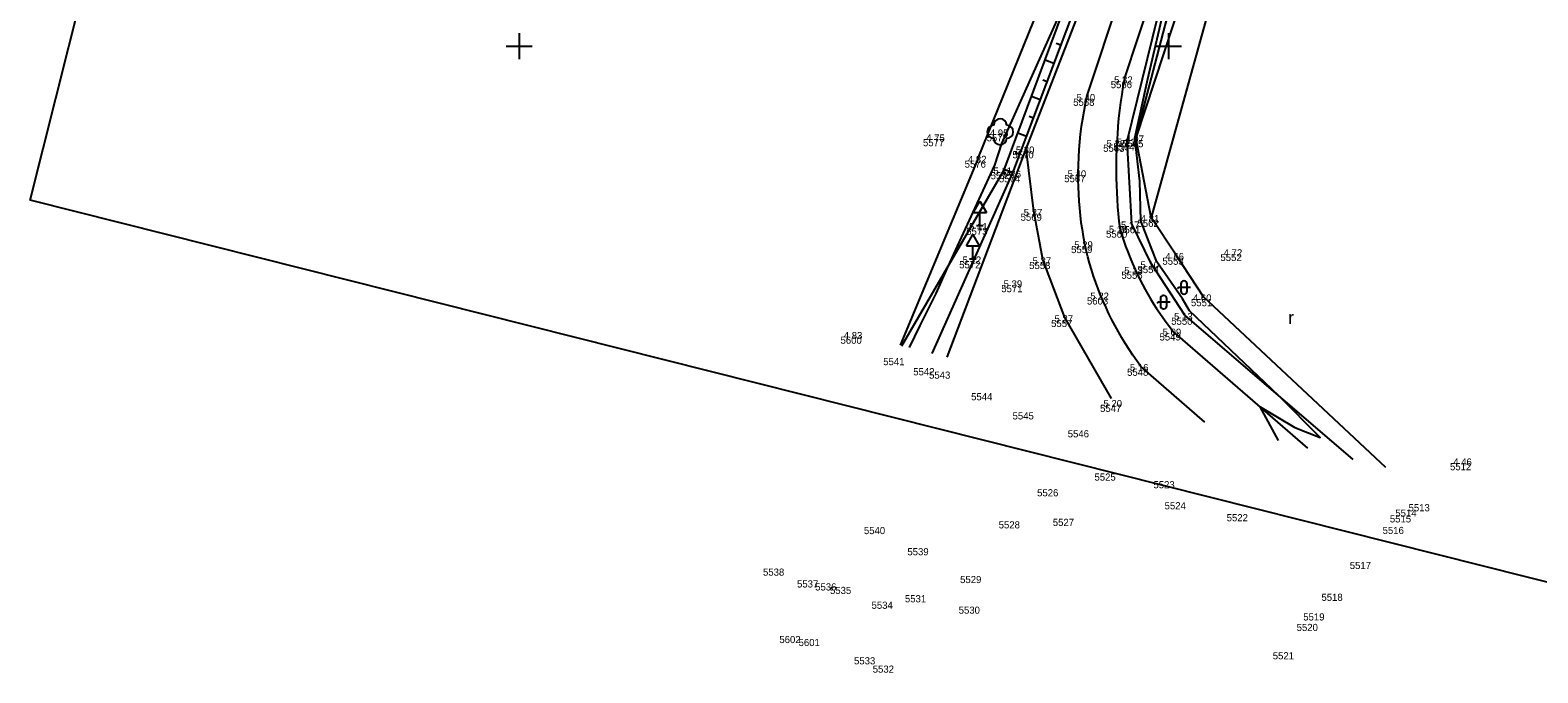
# Model space of a CAD drawing. Extents: x -740053 to -737517, y -1033516 to -1032488.
# Drawn here: x -739137.7 to -739021.5, y -1033448.3 to -1033398.8 of the extents above; entities that cross this region are included whole.
import ezdxf

# ---------------------------------------------------------------- set-up
doc = ezdxf.new("R2010")
doc.units = 0
for name, color, linetype in [('bod-cislo', 7, 'Continuous'), ('bod-oznac', 7, 'Continuous'), ('bod-vyska', 7, 'Continuous'), ('bod-vyska100', 7, 'Continuous'), ('Contours highlighted', 7, 'Continuous'), ('ctv-sit', 7, 'Continuous'), ('dopr-zariz', 7, 'Continuous'), ('osa-komunikace', 7, 'Continuous'), ('Predmety bez rozlišeni', 7, 'Continuous'), ('rozhraní kultůr', 7, 'Continuous'), ('silnice', 7, 'Continuous'), ('Technické šrafy', 7, 'Continuous'), ('Terenni-hrana', 7, 'Continuous'), ('Znacky-kultury', 7, 'Continuous')]:
    doc.layers.add(name, color=color, linetype=linetype)

# ---------------------------------------------------------------- blocks, each defined once
blk = doc.blocks.new('d_znacka')
for p, q in [((-1, 2), (0, 3.73)), ((0, 3.73), (1, 2)), ((-1, 2), (1, 2)), ((-0.5, 0), (0.5, 0)), ((0, 0), (0, 2))]:
    blk.add_line(p, q)
blk = doc.blocks.new('POINT_DISPLAY')
blk.add_line((0, 0), (0, 0))
blk = doc.blocks.new('p_strom')
for centre, start, end in [((-1, 0), 90, 270), ((0, 1), 0, 180), ((1, 0), 270, 90), ((0, -1), 180, 0)]:
    blk.add_arc(centre, 1, start, end)
at = {"rotation": -180}
blk.add_blockref('POINT_DISPLAY', (0, 0), dxfattribs=at)
blk = doc.blocks.new('p_orna')
blk.add_text('r', height=2).set_placement((0, 0))
blk = doc.blocks.new('p_neplod')
for p, q in [((-0.82, 0), (-0.99, -0.18)), ((1, 0), (-0.82, 0)), ((-0.49, 0.56), (-0.49, -0.55)), ((0.05, 1.01), (-0.04, 1.01)), ((0.5, -0.55), (0.5, 0.56)), ((-0.04, -1), (0.05, -1))]:
    blk.add_line(p, q)
for centre, start, end in [((-0.04, 0.56), 90, 180), ((0.05, 0.56), 0, 90), ((-0.04, -0.55), 180, 270), ((0.05, -0.55), 270, 0)]:
    blk.add_arc(centre, 0.45, start, end)
blk = doc.blocks.new('ctvsit')
for p, q in [((2, 0), (-2, 0)), ((0, -2), (0, 2))]:
    blk.add_line(p, q)

msp = doc.modelspace()

# ---------------------------------------------------------------- linework, layer by layer
at = {"layer": 'Contours highlighted'}
for points in [[(-739033.63, -1033329.37), (-739034.16, -1033331.98), (-739033.23, -1033332.91), (-739034.46, -1033336.5), (-739036.42, -1033342.07), (-739043.08, -1033359.62), (-739047.24, -1033370.07), (-739048.86, -1033374.2), (-739055, -1033389.35), (-739056.04, -1033392.04), (-739057.13, -1033394.7), (-739062.85, -1033407.5), (-739063.4, -1033409.17), (-739067.01, -1033417.01), (-739067.91, -1033419.05), (-739069.14, -1033421.5), (-739069.97, -1033423.2)], [(-739041.51, -1033430.37), (-739042.92, -1033427.76), (-739040.25, -1033429.35), (-739038.31, -1033430.14), (-739041.49, -1033426.92), (-739048.38, -1033420.37), (-739048.92, -1033419.44), (-739050.89, -1033416.59), (-739051.32, -1033415.51), (-739052.12, -1033413.44), (-739052.21, -1033410.39), (-739052.59, -1033407.08), (-739051.58, -1033402.52), (-739049.16, -1033392.13), (-739047.08, -1033386.52), (-739041.6, -1033372.35), (-739033.63, -1033352.1), (-739030.53, -1033344.23), (-739026.52, -1033333.46), (-739024.99, -1033329.5)]]:
    msp.add_lwpolyline(points, dxfattribs=at)
at = {"layer": 'osa-komunikace'}
for p, q in [((-739056.28, -1033403.86), (-739051.93, -1033390.71)), ((-739047.18, -1033428.94), (-739052.13, -1033424.65))]:
    msp.add_line(p, q, dxfattribs=at)
for points in [[(-739056.28, -1033403.86), (-739056.41, -1033404.44), (-739056.52, -1033405.02), (-739056.62, -1033405.61), (-739056.71, -1033406.19), (-739056.79, -1033406.78), (-739056.85, -1033407.37), (-739056.9, -1033407.96), (-739056.93, -1033408.55), (-739056.96, -1033409.15), (-739056.97, -1033409.74), (-739056.97, -1033410.29), (-739056.96, -1033410.84), (-739056.93, -1033411.39), (-739056.9, -1033411.94), (-739056.85, -1033412.48), (-739056.8, -1033413.03), (-739056.73, -1033413.57), (-739056.65, -1033414.12), (-739056.56, -1033414.66), (-739056.46, -1033415.2)], [(-739052.13, -1033424.65), (-739052.44, -1033424.22), (-739052.74, -1033423.79), (-739053.03, -1033423.35), (-739053.31, -1033422.91), (-739053.59, -1033422.46), (-739053.85, -1033422), (-739054.1, -1033421.54), (-739054.35, -1033421.07), (-739054.58, -1033420.6), (-739054.8, -1033420.13), (-739055.02, -1033419.64), (-739055.22, -1033419.16), (-739055.41, -1033418.68), (-739055.59, -1033418.19), (-739055.76, -1033417.7), (-739055.92, -1033417.2), (-739056.07, -1033416.71), (-739056.21, -1033416.21), (-739056.34, -1033415.71), (-739056.46, -1033415.2)]]:
    msp.add_lwpolyline(points, dxfattribs=at)
at = {"layer": 'Predmety bez rozlišeni'}
for p, q in [((-739137.66, -1033411.85), (-739112.03, -1033310.03)), ((-738993.66, -1033448.11), (-739137.66, -1033411.85))]:
    msp.add_line(p, q, dxfattribs=at)
at = {"layer": 'rozhraní kultůr'}
msp.add_line((-739045.82, -1033393.35), (-739051.33, -1033413.18), dxfattribs=at)
at = {"layer": 'silnice'}
for p, q in [((-739060.96, -1033407.9), (-739053.99, -1033389.98)), ((-739053.39, -1033402.5), (-739049.79, -1033391.69)), ((-739067.03, -1033423.95), (-739060.96, -1033407.9)), ((-739060.35, -1033412.71), (-739060.96, -1033407.9)), ((-739059.67, -1033416.43), (-739060.35, -1033412.71)), ((-739057.98, -1033420.89), (-739059.67, -1033416.43)), ((-739054.38, -1033427.13), (-739057.98, -1033420.89)), ((-739039.25, -1033430.94), (-739049.65, -1033421.93))]:
    msp.add_line(p, q, dxfattribs=at)
for points in [[(-739053.39, -1033402.5), (-739053.5, -1033403.11), (-739053.59, -1033403.72), (-739053.68, -1033404.33), (-739053.76, -1033404.94), (-739053.83, -1033405.55), (-739053.88, -1033406.17), (-739053.93, -1033406.78), (-739053.97, -1033407.4), (-739054, -1033407.95), (-739054.01, -1033408.5), (-739054.02, -1033409.05), (-739054.02, -1033409.61), (-739054.02, -1033410.16), (-739054, -1033410.71), (-739053.98, -1033411.26), (-739053.95, -1033411.81), (-739053.91, -1033412.36), (-739053.87, -1033412.91), (-739053.81, -1033413.46), (-739053.75, -1033414.01)], [(-739053.75, -1033414.01), (-739053.61, -1033414.47), (-739053.46, -1033414.93), (-739053.3, -1033415.39), (-739053.13, -1033415.84), (-739052.95, -1033416.29), (-739052.77, -1033416.74), (-739052.57, -1033417.18), (-739052.39, -1033417.57), (-739052.2, -1033417.95), (-739052, -1033418.34), (-739051.8, -1033418.72), (-739051.58, -1033419.09), (-739051.37, -1033419.46), (-739051.14, -1033419.83), (-739050.91, -1033420.19), (-739050.67, -1033420.55), (-739050.42, -1033420.9), (-739050.17, -1033421.25), (-739049.91, -1033421.59), (-739049.65, -1033421.93)]]:
    msp.add_lwpolyline(points, dxfattribs=at)
at = {"layer": 'Technické šrafy'}
for p, q in [((-739058.28, -1033399.93), (-739058.63, -1033399.8)), ((-739058.81, -1033401.33), (-739059.5, -1033401.07)), ((-739059.34, -1033402.73), (-739059.68, -1033402.61)), ((-739059.87, -1033404.14), (-739060.54, -1033403.88)), ((-739060.4, -1033405.54), (-739060.73, -1033405.41)), ((-739060.93, -1033406.94), (-739061.59, -1033406.69)), ((-739061.46, -1033408.35), (-739061.79, -1033408.22)), ((-739061.99, -1033409.75), (-739062.64, -1033409.5))]:
    msp.add_line(p, q, dxfattribs=at)
at = {"layer": 'Terenni-hrana'}
for p, q in [((-739064.64, -1033408.62), (-739056.62, -1033388.76)), ((-739062.64, -1033409.51), (-739055.12, -1033389.32)), ((-739061.99, -1033409.75), (-739054.35, -1033389.54)), ((-739053.18, -1033407.3), (-739049.4, -1033391.95)), ((-739052.51, -1033407.05), (-739048.71, -1033392.47)), ((-739047.75, -1033392.58), (-739052.51, -1033407.05)), ((-739052.82, -1033413.67), (-739053.18, -1033407.3)), ((-739051.33, -1033413.18), (-739052.51, -1033407.05)), ((-739064.64, -1033408.62), (-739070.66, -1033423.03)), ((-739070.54, -1033423.06), (-739062.64, -1033409.51)), ((-739068.18, -1033423.66), (-739061.99, -1033409.75)), ((-739049.41, -1033416.1), (-739051.33, -1033413.18)), ((-739051.32, -1033416.74), (-739052.82, -1033413.67)), ((-739048.73, -1033420.72), (-739051.32, -1033416.74)), ((-739047.29, -1033419.29), (-739049.41, -1033416.1)), ((-739033.26, -1033432.45), (-739047.29, -1033419.29)), ((-739035.76, -1033431.82), (-739048.73, -1033420.72))]:
    msp.add_line(p, q, dxfattribs=at)

# ---------------------------------------------------------------- block references
at = {"layer": 'bod-oznac'}
for p in [(-739053.39, -1033402.5), (-739056.28, -1033403.86), (-739062.95, -1033406.59), (-739067.85, -1033406.97), (-739053.97, -1033407.4), (-739053.18, -1033407.3), (-739052.51, -1033407.05), (-739064.64, -1033408.62), (-739060.96, -1033407.9), (-739062.64, -1033409.51), (-739061.99, -1033409.75), (-739056.97, -1033409.74), (-739060.35, -1033412.71), (-739051.33, -1033413.18), (-739064.52, -1033413.8), (-739053.75, -1033414.01), (-739052.82, -1033413.67), (-739056.46, -1033415.2), (-739044.94, -1033415.81), (-739065.06, -1033416.37), (-739059.67, -1033416.43), (-739051.32, -1033416.74), (-739049.41, -1033416.1), (-739061.9, -1033418.21), (-739052.57, -1033417.18), (-739055.22, -1033419.16), (-739047.29, -1033419.29), (-739057.98, -1033420.89), (-739048.73, -1033420.72), (-739049.65, -1033421.93), (-739052.13, -1033424.65), (-739027.26, -1033431.92)]:
    msp.add_blockref('POINT_DISPLAY', p, dxfattribs=at)
at = {"layer": 'ctv-sit', "xscale": 0.5, "yscale": 0.5, "rotation": 180}
for p in [(-739100, -1033400), (-739050, -1033400)]:
    msp.add_blockref('ctvsit', p, dxfattribs=at)
at = {"layer": 'dopr-zariz', "xscale": 0.5, "yscale": 0.5}
for p in [(-739064.52, -1033413.8), (-739065.06, -1033416.37)]:
    msp.add_blockref('d_znacka', p, dxfattribs=at)
at = {"layer": 'Znacky-kultury', "xscale": 0.5, "yscale": 0.5}
for name, p in [('p_strom', (-739062.95, -1033406.59)), ('p_neplod', (-739048.8, -1033418.58)), ('p_neplod', (-739050.37, -1033419.71)), ('p_orna', (-739040.77, -1033421.4))]:
    msp.add_blockref(name, p, dxfattribs=at)

# ---------------------------------------------------------------- texts
at = {"layer": 'bod-cislo'}
for s, p in [('5566', (-739054.44, -1033403.23)), ('5568', (-739057.33, -1033404.59)), ('5577', (-739068.9, -1033407.7)), ('5578', (-739064, -1033407.32)), ('5563', (-739055.02, -1033408.13)), ('5564', (-739054.24, -1033408.03)), ('5565', (-739053.56, -1033407.78)), ('5576', (-739065.69, -1033409.35)), ('5570', (-739062.01, -1033408.63)), ('5575', (-739063.69, -1033410.24)), ('5574', (-739063.05, -1033410.48)), ('5567', (-739058.02, -1033410.47)), ('5569', (-739061.38, -1033413.44)), ('5562', (-739052.38, -1033413.91)), ('5573', (-739065.57, -1033414.53)), ('5560', (-739054.8, -1033414.74)), ('5561', (-739053.79, -1033414.4)), ('5559', (-739057.49, -1033415.93)), ('5572', (-739066.11, -1033417.1)), ('5558', (-739060.72, -1033417.16)), ('5554', (-739052.38, -1033417.47)), ('5553', (-739050.46, -1033416.83)), ('5552', (-739045.99, -1033416.54)), ('5555', (-739053.62, -1033417.91)), ('5571', (-739062.87, -1033418.94)), ('5603', (-739056.27, -1033419.89)), ('5551', (-739048.26, -1033420.02)), ('5557', (-739059.03, -1033421.62)), ('5550', (-739049.78, -1033421.45)), ('5600', (-739075.25, -1033422.91)), ('5549', (-739050.68, -1033422.66)), ('5541', (-739071.96, -1033424.56)), ('5542', (-739069.65, -1033425.34)), ('5543', (-739068.43, -1033425.6)), ('5548', (-739053.18, -1033425.38)), ('5544', (-739065.19, -1033427.26)), ('5545', (-739062, -1033428.74)), ('5547', (-739055.26, -1033428.16)), ('5546', (-739057.75, -1033430.12)), ('5512', (-739028.31, -1033432.65)), ('5525', (-739055.69, -1033433.45)), ('5526', (-739060.11, -1033434.66)), ('5523', (-739051.15, -1033434.04)), ('5524', (-739050.29, -1033435.66)), ('5514', (-739032.52, -1033436.23)), ('5513', (-739031.5, -1033435.81)), ('5528', (-739063.07, -1033437.13)), ('5527', (-739058.9, -1033436.94)), ('5522', (-739045.51, -1033436.58)), ('5515', (-739032.94, -1033436.67)), ('5540', (-739073.45, -1033437.57)), ('5516', (-739033.5, -1033437.56)), ('5539', (-739070.1, -1033439.2)), ('5538', (-739081.22, -1033440.77)), ('5517', (-739036.03, -1033440.26)), ('5537', (-739078.6, -1033441.68)), ('5536', (-739077.2, -1033441.91)), ('5529', (-739066.04, -1033441.34)), ('5535', (-739076.06, -1033442.18)), ('5531', (-739070.29, -1033442.82)), ('5518', (-739038.21, -1033442.71)), ('5534', (-739072.86, -1033443.32)), ('5530', (-739066.15, -1033443.7)), ('5519', (-739039.61, -1033444.22)), ('5520', (-739040.12, -1033445.03)), ('5602', (-739079.96, -1033445.96)), ('5601', (-739078.48, -1033446.19)), ('5533', (-739074.21, -1033447.6)), ('5521', (-739041.96, -1033447.21)), ('5532', (-739072.77, -1033448.24))]:
    msp.add_text(s, height=0.55, dxfattribs=at).set_placement(p)
at = {"layer": 'bod-vyska'}
for s, p in [('5 32', (-739054.18, -1033402.87)), ('5 40', (-739057.07, -1033404.23)), ('4 95', (-739063.75, -1033406.96)), ('4 75', (-739068.65, -1033407.34)), ('5 30', (-739061.75, -1033408.27)), ('5 22', (-739054.76, -1033407.77)), ('5 21', (-739053.97, -1033407.67)), ('4 97', (-739053.31, -1033407.42)), ('4 82', (-739065.44, -1033408.99)), ('5 11', (-739063.47, -1033409.88)), ('5 26', (-739062.78, -1033410.12)), ('5 40', (-739057.76, -1033410.11)), ('5 11', (-739065.35, -1033414.17)), ('5 37', (-739061.14, -1033413.08)), ('5 17', (-739053.65, -1033414.04)), ('4 81', (-739052.13, -1033413.55)), ('5 18', (-739054.58, -1033414.38)), ('5 29', (-739057.25, -1033415.57)), ('4 66', (-739050.23, -1033416.47)), ('4 72', (-739045.74, -1033416.18)), ('5 22', (-739065.85, -1033416.74)), ('5 37', (-739060.46, -1033416.8)), ('5 13', (-739053.4, -1033417.55)), ('5 10', (-739052.15, -1033417.11)), ('5 39', (-739062.69, -1033418.58)), ('5 22', (-739056.01, -1033419.52)), ('4 60', (-739048.11, -1033419.66)), ('5 13', (-739049.56, -1033421.09)), ('5 27', (-739058.77, -1033421.26)), ('5 09', (-739050.44, -1033422.3)), ('4 83', (-739075, -1033422.55)), ('5 16', (-739052.96, -1033425.02)), ('5 20', (-739055, -1033427.79)), ('4 46', (-739028.06, -1033432.29))]:
    msp.add_text(s, height=0.55, dxfattribs=at).set_placement(p)
at = {"layer": 'bod-vyska100'}
for s, p in [('305 32', (-739053.56, -1033402.53)), ('305 40', (-739056.45, -1033403.89)), ('304 95', (-739063.12, -1033406.62)), ('304 75', (-739068.02, -1033407)), ('305 22', (-739054.14, -1033407.43)), ('305 21', (-739053.35, -1033407.33)), ('304 97', (-739052.68, -1033407.08)), ('304 82', (-739064.81, -1033408.65)), ('305 30', (-739061.13, -1033407.93)), ('305 11', (-739062.81, -1033409.54)), ('305 26', (-739062.16, -1033409.78)), ('305 40', (-739057.14, -1033409.77)), ('305 37', (-739060.52, -1033412.74)), ('304 81', (-739051.5, -1033413.21)), ('305 11', (-739064.69, -1033413.83)), ('305 18', (-739053.92, -1033414.04)), ('305 17', (-739052.99, -1033413.7)), ('305 29', (-739056.63, -1033415.23)), ('304 72', (-739045.11, -1033415.84)), ('305 22', (-739065.23, -1033416.4)), ('305 37', (-739059.84, -1033416.46)), ('305 10', (-739051.49, -1033416.77)), ('304 66', (-739049.58, -1033416.13)), ('305 39', (-739062.07, -1033418.24)), ('305 13', (-739052.74, -1033417.21)), ('305 22', (-739055.39, -1033419.19)), ('304 60', (-739047.46, -1033419.32)), ('305 27', (-739058.15, -1033420.92)), ('305 13', (-739048.9, -1033420.75)), ('304 83', (-739074.37, -1033422.21)), ('305 09', (-739049.82, -1033421.96)), ('305 16', (-739052.3, -1033424.68)), ('304 46', (-739027.43, -1033431.95))]:
    msp.add_text(s, height=0.05, dxfattribs=at).set_placement(p)

doc.saveas('drawing.dxf')
